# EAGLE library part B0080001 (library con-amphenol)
AMPHENOL CONNECTOR
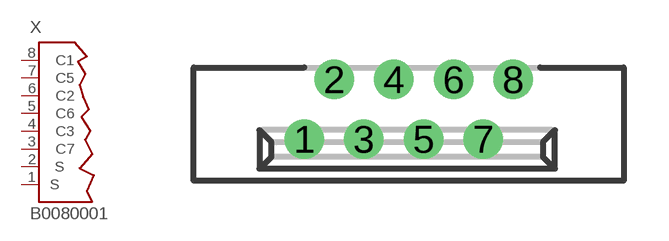
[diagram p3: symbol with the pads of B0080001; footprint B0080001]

Designator prefix X

## B0080001 (OC_FARNELL: unknown; OC_NEWARK: unknown)  [B0080001]
1  S1  pas
2  S2  pas
3  C7  pas
4  C3  pas
5  C6  pas
6  C2  pas
7  C5  pas
8  C1  pas

## Footprint B0080001 (pad centres in mm)
AMPHENOL CONNECTOR
drill 0.813 round: 1 -3.5,-1; 2 -2.5,1; 3 -1.5,-1; 4 -0.5,1; 5 0.5,-1; 6 1.5,1; 7 2.5,-1; 8 3.5,1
